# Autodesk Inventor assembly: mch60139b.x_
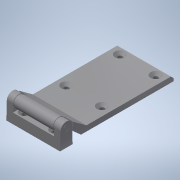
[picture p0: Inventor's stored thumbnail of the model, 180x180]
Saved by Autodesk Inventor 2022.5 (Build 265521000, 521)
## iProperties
Part Number: mch60139b.x_
Material: 一般
Document SubType Name: Assembly
Designer: ImaoCorp
Sending System: SOLIDWORKS 2017-2017317
MC: AMD64
MC_MODEL: Intel64 Family 6 Model 60 Stepping 3, GenuineIntel
OS: Windows_NT
FRU: Parasolid Version 29.0, build 201,  4-17-2017
FORMAT: text
GUISE: transmit
KEY: mch60139b
FILE: mch60139b.x_t
DATE: Fri Jul 26 11:41:10 2019
Author: ImaoCorp
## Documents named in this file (4)
- X:\14_SW2022-Inv2022\00_全2023-1023新製品(TCC)まで\m\mch60139b\MCH60139B.iam
- X:\14_SW2022-Inv2022\00_全2023-1023新製品(TCC)まで\m\mch60139b\mch60139b_01.ipt
- X:\14_SW2022-Inv2022\00_全2023-1023新製品(TCC)まで\m\mch60139b\mch60139b_02.ipt
- X:\14_SW2022-Inv2022\00_全2023-1023新製品(TCC)まで\m\mch60139b\mch60139b_03.ipt
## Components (3 placed, 3 different names)
1. mch60139b_01
2. mch60139b_02
3. mch60139b_03
